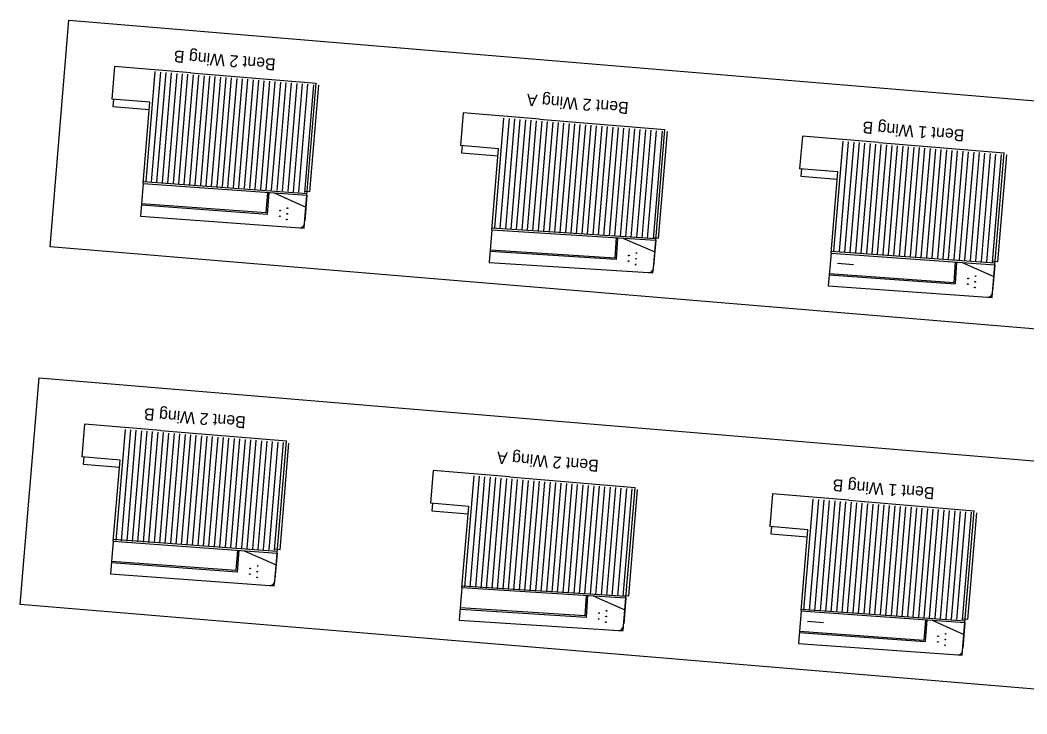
# Model space of a CAD drawing. Extents: x 1313815 to 1314857, y 2089008 to 2089414.
# Drawn here: x 1314567 to 1314659, y 2089331.7 to 2089395.1 of the extents above; entities that cross this region are included whole.
import ezdxf

# ---------------------------------------------------------------- set-up
doc = ezdxf.new("R2010")
doc.units = 0
for name, color, linetype in [('B-Gen-Hidden', 7, 'Continuous'), ('B-Gen-Rebar', 7, 'Continuous'), ('B-Gen-Viewport', 7, 'Continuous'), ('B-Sub-Abutment Cap (Hidden)', 7, 'Continuous'), ('B-Sub-Wingwall', 7, 'Continuous'), ('B-Super-Parapet', 7, 'Continuous')]:
    doc.layers.add(name, color=color, linetype=linetype)

msp = doc.modelspace()

# ---------------------------------------------------------------- linework, layer by layer
at = {"layer": 'B-Gen-Hidden'}
for p, q in [((1314593.477, 2089379.402), (1314594.292, 2089389.161)), ((1314625.332, 2089375.158), (1314626.147, 2089384.917)), ((1314656.32, 2089373.03), (1314657.135, 2089382.789)), ((1314578.254, 2089380.357), (1314593.214, 2089379.263)), ((1314578.24, 2089380.191), (1314593.201, 2089379.097)), ((1314589.585, 2089379.361), (1314589.448, 2089377.491)), ((1314589.71, 2089379.352), (1314589.564, 2089377.358)), ((1314593.477, 2089379.402), (1314592.979, 2089379.444)), ((1314590.208, 2089379.316), (1314593.11, 2089378.017)), ((1314589.564, 2089377.358), (1314578.073, 2089378.198)), ((1314589.448, 2089377.491), (1314578.084, 2089378.323)), ((1314592.542, 2089376.137), (1314592.951, 2089376.107)), ((1314592.951, 2089376.107), (1314592.985, 2089376.518)), ((1314610.095, 2089375.947), (1314625.068, 2089374.996)), ((1314610.109, 2089376.113), (1314625.081, 2089375.163)), ((1314621.449, 2089375.226), (1314621.33, 2089373.355)), ((1314621.574, 2089375.218), (1314621.447, 2089373.222)), ((1314622.073, 2089375.187), (1314624.977, 2089373.917)), ((1314625.332, 2089375.158), (1314624.834, 2089375.2)), ((1314621.447, 2089373.222), (1314609.928, 2089373.954)), ((1314621.33, 2089373.355), (1314609.939, 2089374.078)), ((1314641.097, 2089373.985), (1314656.059, 2089372.912)), ((1314641.083, 2089373.819), (1314656.046, 2089372.746)), ((1314652.431, 2089373.005), (1314652.297, 2089371.135)), ((1314652.556, 2089372.996), (1314652.413, 2089371.002)), ((1314653.053, 2089372.961), (1314655.955, 2089371.667)), ((1314656.32, 2089373.03), (1314655.822, 2089373.071)), ((1314624.409, 2089372.033), (1314624.818, 2089372.007)), ((1314624.818, 2089372.007), (1314624.852, 2089372.414)), ((1314641.663, 2089372.883), (1314643.135, 2089372.76)), ((1314640.917, 2089371.825), (1314652.413, 2089371.002)), ((1314640.927, 2089371.95), (1314652.297, 2089371.135)), ((1314655.796, 2089369.757), (1314655.83, 2089370.169)), ((1314655.387, 2089369.786), (1314655.796, 2089369.757)), ((1314590.747, 2089346.693), (1314591.561, 2089356.452)), ((1314622.602, 2089342.449), (1314623.416, 2089352.208)), ((1314653.59, 2089340.321), (1314654.404, 2089350.079)), ((1314575.509, 2089347.482), (1314590.47, 2089346.388)), ((1314575.523, 2089347.648), (1314590.484, 2089346.554)), ((1314586.855, 2089346.652), (1314586.718, 2089344.782)), ((1314586.979, 2089346.643), (1314586.833, 2089344.648)), ((1314587.478, 2089346.607), (1314590.38, 2089345.308)), ((1314590.747, 2089346.693), (1314590.248, 2089346.735)), ((1314586.833, 2089344.648), (1314575.343, 2089345.489)), ((1314586.718, 2089344.782), (1314575.353, 2089345.613)), ((1314590.221, 2089343.398), (1314590.255, 2089343.809)), ((1314589.811, 2089343.428), (1314590.221, 2089343.398)), ((1314607.364, 2089343.238), (1314622.337, 2089342.287)), ((1314607.378, 2089343.404), (1314622.351, 2089342.453)), ((1314618.719, 2089342.517), (1314618.6, 2089340.646)), ((1314618.844, 2089342.509), (1314618.717, 2089340.513)), ((1314619.343, 2089342.477), (1314622.247, 2089341.208)), ((1314622.602, 2089342.449), (1314622.103, 2089342.491)), ((1314618.717, 2089340.513), (1314607.198, 2089341.244)), ((1314618.6, 2089340.646), (1314607.208, 2089341.369)), ((1314638.353, 2089341.109), (1314653.315, 2089340.037)), ((1314638.366, 2089341.275), (1314653.329, 2089340.203)), ((1314638.933, 2089340.174), (1314640.405, 2089340.051)), ((1314649.701, 2089340.296), (1314649.567, 2089338.426)), ((1314649.826, 2089340.287), (1314649.683, 2089338.292)), ((1314650.323, 2089340.251), (1314653.225, 2089338.957)), ((1314653.59, 2089340.321), (1314653.091, 2089340.362)), ((1314621.678, 2089339.324), (1314622.088, 2089339.298)), ((1314622.088, 2089339.298), (1314622.122, 2089339.705)), ((1314638.186, 2089339.116), (1314649.683, 2089338.292)), ((1314638.197, 2089339.241), (1314649.567, 2089338.426)), ((1314652.656, 2089337.077), (1314653.066, 2089337.047)), ((1314653.066, 2089337.047), (1314653.1, 2089337.46))]:
    msp.add_line(p, q, dxfattribs=at)
at = {"layer": 'B-Gen-Rebar'}
for p, q in [((1314578.505, 2089380.361), (1314579.344, 2089390.409)), ((1314579.004, 2089380.326), (1314579.842, 2089390.367)), ((1314579.502, 2089380.292), (1314580.34, 2089390.326)), ((1314580.001, 2089380.257), (1314580.838, 2089390.284)), ((1314580.5, 2089380.223), (1314581.337, 2089390.243)), ((1314580.999, 2089380.188), (1314581.835, 2089390.201)), ((1314581.498, 2089380.154), (1314582.333, 2089390.159)), ((1314581.997, 2089380.119), (1314582.831, 2089390.118)), ((1314582.496, 2089380.085), (1314583.33, 2089390.076)), ((1314582.995, 2089380.051), (1314583.828, 2089390.035)), ((1314583.493, 2089380.016), (1314584.326, 2089389.993)), ((1314583.992, 2089379.982), (1314584.824, 2089389.951)), ((1314584.491, 2089379.947), (1314585.323, 2089389.91)), ((1314584.99, 2089379.913), (1314585.821, 2089389.868)), ((1314585.489, 2089379.878), (1314586.319, 2089389.827)), ((1314585.988, 2089379.844), (1314586.818, 2089389.785)), ((1314586.487, 2089379.81), (1314587.316, 2089389.743)), ((1314586.985, 2089379.775), (1314587.814, 2089389.702)), ((1314587.484, 2089379.741), (1314588.312, 2089389.66)), ((1314587.983, 2089379.706), (1314588.811, 2089389.619)), ((1314588.482, 2089379.672), (1314589.309, 2089389.577)), ((1314588.981, 2089379.637), (1314589.807, 2089389.535)), ((1314589.48, 2089379.603), (1314590.305, 2089389.494)), ((1314589.979, 2089379.569), (1314590.804, 2089389.452)), ((1314590.478, 2089379.534), (1314591.302, 2089389.411)), ((1314590.976, 2089379.5), (1314591.8, 2089389.369)), ((1314591.475, 2089379.465), (1314592.298, 2089389.328)), ((1314591.974, 2089379.431), (1314592.797, 2089389.286)), ((1314592.473, 2089379.396), (1314593.295, 2089389.244)), ((1314593.793, 2089389.203), (1314592.972, 2089379.362)), ((1314610.36, 2089376.117), (1314611.199, 2089386.165)), ((1314610.859, 2089376.082), (1314611.697, 2089386.123)), ((1314611.358, 2089376.048), (1314612.195, 2089386.082)), ((1314611.856, 2089376.013), (1314612.693, 2089386.04)), ((1314612.355, 2089375.979), (1314613.192, 2089385.999)), ((1314612.854, 2089375.944), (1314613.69, 2089385.957)), ((1314613.353, 2089375.91), (1314614.188, 2089385.915)), ((1314613.852, 2089375.875), (1314614.686, 2089385.874)), ((1314614.351, 2089375.841), (1314615.185, 2089385.832)), ((1314614.85, 2089375.807), (1314615.683, 2089385.791)), ((1314615.348, 2089375.772), (1314616.181, 2089385.749)), ((1314615.847, 2089375.738), (1314616.679, 2089385.707)), ((1314616.346, 2089375.703), (1314617.178, 2089385.666)), ((1314616.845, 2089375.669), (1314617.676, 2089385.624)), ((1314617.344, 2089375.634), (1314618.174, 2089385.583)), ((1314617.843, 2089375.6), (1314618.673, 2089385.541)), ((1314618.342, 2089375.566), (1314619.171, 2089385.499)), ((1314618.84, 2089375.531), (1314619.669, 2089385.458)), ((1314619.339, 2089375.497), (1314620.167, 2089385.416)), ((1314619.838, 2089375.462), (1314620.666, 2089385.375)), ((1314620.337, 2089375.428), (1314621.164, 2089385.333)), ((1314620.836, 2089375.393), (1314621.662, 2089385.291)), ((1314621.335, 2089375.359), (1314622.16, 2089385.25)), ((1314621.834, 2089375.325), (1314622.659, 2089385.208)), ((1314622.333, 2089375.29), (1314623.157, 2089385.167)), ((1314622.831, 2089375.256), (1314623.655, 2089385.125)), ((1314623.33, 2089375.221), (1314624.153, 2089385.084)), ((1314623.829, 2089375.187), (1314624.652, 2089385.042)), ((1314624.328, 2089375.152), (1314625.15, 2089385)), ((1314625.648, 2089384.959), (1314624.827, 2089375.118)), ((1314641.348, 2089373.988), (1314642.187, 2089384.036)), ((1314641.847, 2089373.953), (1314642.685, 2089383.995)), ((1314642.346, 2089373.919), (1314643.183, 2089383.953)), ((1314642.844, 2089373.885), (1314643.681, 2089383.912)), ((1314643.343, 2089373.85), (1314644.18, 2089383.87)), ((1314643.842, 2089373.816), (1314644.678, 2089383.828)), ((1314644.341, 2089373.781), (1314645.176, 2089383.787)), ((1314644.84, 2089373.747), (1314645.675, 2089383.745)), ((1314645.339, 2089373.712), (1314646.173, 2089383.704)), ((1314645.838, 2089373.678), (1314646.671, 2089383.662)), ((1314646.337, 2089373.644), (1314647.169, 2089383.62)), ((1314646.835, 2089373.609), (1314647.668, 2089383.579)), ((1314647.334, 2089373.575), (1314648.166, 2089383.537)), ((1314647.833, 2089373.54), (1314648.664, 2089383.496)), ((1314648.332, 2089373.506), (1314649.162, 2089383.454)), ((1314648.831, 2089373.471), (1314649.661, 2089383.412)), ((1314649.33, 2089373.437), (1314650.159, 2089383.371)), ((1314649.829, 2089373.403), (1314650.657, 2089383.329)), ((1314650.327, 2089373.368), (1314651.155, 2089383.288)), ((1314650.826, 2089373.334), (1314651.654, 2089383.246)), ((1314651.325, 2089373.299), (1314652.152, 2089383.204)), ((1314651.824, 2089373.265), (1314652.65, 2089383.163)), ((1314652.323, 2089373.23), (1314653.149, 2089383.121)), ((1314652.822, 2089373.196), (1314653.647, 2089383.08)), ((1314653.321, 2089373.162), (1314654.145, 2089383.038)), ((1314653.82, 2089373.127), (1314654.643, 2089382.997)), ((1314654.318, 2089373.093), (1314655.142, 2089382.955)), ((1314654.817, 2089373.058), (1314655.64, 2089382.913)), ((1314655.316, 2089373.024), (1314656.138, 2089382.872)), ((1314656.636, 2089382.83), (1314655.815, 2089372.989)), ((1314575.766, 2089347.549), (1314576.613, 2089357.7)), ((1314576.265, 2089347.519), (1314577.111, 2089357.658)), ((1314576.764, 2089347.488), (1314577.61, 2089357.616)), ((1314577.263, 2089347.457), (1314578.108, 2089357.575)), ((1314577.763, 2089347.426), (1314578.606, 2089357.533)), ((1314578.262, 2089347.395), (1314579.105, 2089357.492)), ((1314578.761, 2089347.364), (1314579.603, 2089357.45)), ((1314579.26, 2089347.333), (1314580.101, 2089357.409)), ((1314579.759, 2089347.302), (1314580.599, 2089357.367)), ((1314580.258, 2089347.271), (1314581.098, 2089357.325)), ((1314580.757, 2089347.24), (1314581.596, 2089357.284)), ((1314581.257, 2089347.209), (1314582.094, 2089357.242)), ((1314581.756, 2089347.178), (1314582.592, 2089357.201)), ((1314582.255, 2089347.147), (1314583.091, 2089357.159)), ((1314582.754, 2089347.116), (1314583.589, 2089357.117)), ((1314583.253, 2089347.085), (1314584.087, 2089357.076)), ((1314583.752, 2089347.054), (1314584.585, 2089357.034)), ((1314584.252, 2089347.023), (1314585.084, 2089356.993)), ((1314584.751, 2089346.992), (1314585.582, 2089356.951)), ((1314585.25, 2089346.961), (1314586.08, 2089356.909)), ((1314585.749, 2089346.93), (1314586.579, 2089356.868)), ((1314586.248, 2089346.899), (1314587.077, 2089356.826)), ((1314586.747, 2089346.868), (1314587.575, 2089356.785)), ((1314587.246, 2089346.837), (1314588.073, 2089356.743)), ((1314587.746, 2089346.806), (1314588.572, 2089356.701)), ((1314588.245, 2089346.775), (1314589.07, 2089356.66)), ((1314588.744, 2089346.745), (1314589.568, 2089356.618)), ((1314589.243, 2089346.714), (1314590.066, 2089356.577)), ((1314589.742, 2089346.683), (1314590.565, 2089356.535)), ((1314590.241, 2089346.652), (1314591.063, 2089356.493)), ((1314607.621, 2089343.305), (1314608.468, 2089353.456)), ((1314608.12, 2089343.275), (1314608.966, 2089353.414)), ((1314608.619, 2089343.244), (1314609.465, 2089353.372)), ((1314609.118, 2089343.213), (1314609.963, 2089353.331)), ((1314609.618, 2089343.182), (1314610.461, 2089353.289)), ((1314610.117, 2089343.151), (1314610.96, 2089353.248)), ((1314610.616, 2089343.12), (1314611.458, 2089353.206)), ((1314611.115, 2089343.089), (1314611.956, 2089353.165)), ((1314611.614, 2089343.058), (1314612.454, 2089353.123)), ((1314612.113, 2089343.027), (1314612.953, 2089353.081)), ((1314612.612, 2089342.996), (1314613.451, 2089353.04)), ((1314613.112, 2089342.965), (1314613.949, 2089352.998)), ((1314613.611, 2089342.934), (1314614.447, 2089352.957)), ((1314614.11, 2089342.903), (1314614.946, 2089352.915)), ((1314614.609, 2089342.872), (1314615.444, 2089352.873)), ((1314615.108, 2089342.841), (1314615.942, 2089352.832)), ((1314615.607, 2089342.81), (1314616.44, 2089352.79)), ((1314616.107, 2089342.779), (1314616.939, 2089352.749)), ((1314616.606, 2089342.748), (1314617.437, 2089352.707)), ((1314617.105, 2089342.717), (1314617.935, 2089352.665)), ((1314617.604, 2089342.686), (1314618.434, 2089352.624)), ((1314618.103, 2089342.655), (1314618.932, 2089352.582)), ((1314618.602, 2089342.624), (1314619.43, 2089352.541)), ((1314619.102, 2089342.593), (1314619.928, 2089352.499)), ((1314619.601, 2089342.562), (1314620.427, 2089352.457)), ((1314620.1, 2089342.532), (1314620.925, 2089352.416)), ((1314620.599, 2089342.501), (1314621.423, 2089352.374)), ((1314621.098, 2089342.47), (1314621.921, 2089352.333)), ((1314621.597, 2089342.439), (1314622.42, 2089352.291)), ((1314622.096, 2089342.408), (1314622.918, 2089352.25)), ((1314638.609, 2089341.177), (1314639.456, 2089351.327)), ((1314639.108, 2089341.146), (1314639.955, 2089351.285)), ((1314639.607, 2089341.115), (1314640.453, 2089351.244)), ((1314640.107, 2089341.084), (1314640.951, 2089351.202)), ((1314640.606, 2089341.053), (1314641.449, 2089351.161)), ((1314641.105, 2089341.022), (1314641.948, 2089351.119)), ((1314641.604, 2089340.991), (1314642.446, 2089351.078)), ((1314642.103, 2089340.96), (1314642.944, 2089351.036)), ((1314642.602, 2089340.929), (1314643.442, 2089350.994)), ((1314643.101, 2089340.898), (1314643.941, 2089350.953)), ((1314643.601, 2089340.867), (1314644.439, 2089350.911)), ((1314644.1, 2089340.836), (1314644.937, 2089350.87)), ((1314644.599, 2089340.805), (1314645.436, 2089350.828)), ((1314645.098, 2089340.774), (1314645.934, 2089350.786)), ((1314645.597, 2089340.743), (1314646.432, 2089350.745)), ((1314646.096, 2089340.712), (1314646.93, 2089350.703)), ((1314646.596, 2089340.682), (1314647.429, 2089350.662)), ((1314647.095, 2089340.651), (1314647.927, 2089350.62)), ((1314647.594, 2089340.62), (1314648.425, 2089350.578)), ((1314648.093, 2089340.589), (1314648.923, 2089350.537)), ((1314648.592, 2089340.558), (1314649.422, 2089350.495)), ((1314649.091, 2089340.527), (1314649.92, 2089350.454)), ((1314649.59, 2089340.496), (1314650.418, 2089350.412)), ((1314650.09, 2089340.465), (1314650.916, 2089350.37)), ((1314650.589, 2089340.434), (1314651.415, 2089350.329)), ((1314651.088, 2089340.403), (1314651.913, 2089350.287)), ((1314651.587, 2089340.372), (1314652.411, 2089350.246)), ((1314652.086, 2089340.341), (1314652.91, 2089350.204)), ((1314652.585, 2089340.31), (1314653.408, 2089350.162)), ((1314653.085, 2089340.279), (1314653.906, 2089350.121))]:
    msp.add_line(p, q, dxfattribs=at)
for centre, radius in [((1314590.75, 2089377.701), 0.0313), ((1314591.432, 2089377.921), 0.0312), ((1314590.719, 2089377.181), 0.0313), ((1314591.368, 2089376.88), 0.0313), ((1314591.4, 2089377.4), 0.0313), ((1314623.299, 2089373.82), 0.0312), ((1314622.586, 2089373.08), 0.0313), ((1314622.617, 2089373.6), 0.0313), ((1314623.267, 2089373.3), 0.0313), ((1314623.235, 2089372.779), 0.0313), ((1314653.607, 2089371.494), 0.0313), ((1314654.257, 2089371.193), 0.0313), ((1314654.289, 2089371.713), 0.0312), ((1314653.576, 2089370.973), 0.0313), ((1314654.225, 2089370.673), 0.0313), ((1314587.988, 2089344.471), 0.0313), ((1314588.02, 2089344.992), 0.0313), ((1314588.67, 2089344.691), 0.0313), ((1314588.701, 2089345.211), 0.0312), ((1314588.638, 2089344.17), 0.0313), ((1314619.887, 2089340.891), 0.0313), ((1314620.568, 2089341.111), 0.0312), ((1314619.855, 2089340.371), 0.0313), ((1314620.505, 2089340.07), 0.0313), ((1314620.537, 2089340.59), 0.0313), ((1314651.558, 2089339.004), 0.0312), ((1314650.845, 2089338.264), 0.0313), ((1314650.877, 2089338.785), 0.0313), ((1314651.495, 2089337.963), 0.0313), ((1314651.527, 2089338.484), 0.0313)]:
    msp.add_circle(centre, radius, dxfattribs=at)
at = {"layer": 'B-Gen-Viewport'}
for points in [[(1314689.435, 2089364.398), (1314569.73, 2089374.39), (1314571.46, 2089395.114), (1314691.165, 2089385.122)], [(1314686.705, 2089331.689), (1314567, 2089341.681), (1314568.729, 2089362.405), (1314688.435, 2089352.413)]]:
    msp.add_lwpolyline(points, close=True, dxfattribs=at)
at = {"layer": 'B-Sub-Wingwall'}
for p, q in [((1314575.62, 2089390.887), (1314575.371, 2089387.897)), ((1314582.596, 2089390.305), (1314575.62, 2089390.887)), ((1314582.596, 2089390.305), (1314594.056, 2089389.348)), ((1314593.201, 2089379.097), (1314594.056, 2089389.348)), ((1314578.859, 2089387.606), (1314575.371, 2089387.897)), ((1314575.537, 2089387.883), (1314575.481, 2089387.219)), ((1314575.481, 2089387.219), (1314578.803, 2089386.942)), ((1314578.24, 2089380.191), (1314578.859, 2089387.606)), ((1314607.475, 2089386.643), (1314607.226, 2089383.653)), ((1314614.451, 2089386.061), (1314607.475, 2089386.643)), ((1314614.451, 2089386.061), (1314625.911, 2089385.104)), ((1314625.068, 2089374.996), (1314625.911, 2089385.104)), ((1314638.464, 2089384.514), (1314638.214, 2089381.525)), ((1314645.439, 2089383.932), (1314638.464, 2089384.514)), ((1314610.714, 2089383.362), (1314607.226, 2089383.653)), ((1314607.392, 2089383.639), (1314607.336, 2089382.975)), ((1314610.095, 2089375.947), (1314610.714, 2089383.362)), ((1314645.439, 2089383.932), (1314656.899, 2089382.975)), ((1314607.336, 2089382.975), (1314610.658, 2089382.698)), ((1314656.046, 2089372.746), (1314656.899, 2089382.975)), ((1314641.702, 2089381.234), (1314638.214, 2089381.525)), ((1314638.38, 2089381.511), (1314638.325, 2089380.847)), ((1314641.083, 2089373.819), (1314641.702, 2089381.234)), ((1314638.325, 2089380.847), (1314641.646, 2089380.569)), ((1314572.89, 2089358.178), (1314572.64, 2089355.188)), ((1314579.866, 2089357.595), (1314572.89, 2089358.178)), ((1314579.866, 2089357.595), (1314591.326, 2089356.639)), ((1314590.47, 2089346.388), (1314591.326, 2089356.639)), ((1314576.128, 2089354.897), (1314572.64, 2089355.188)), ((1314572.807, 2089355.174), (1314572.751, 2089354.51)), ((1314575.509, 2089347.482), (1314576.128, 2089354.897)), ((1314572.751, 2089354.51), (1314576.073, 2089354.233)), ((1314604.745, 2089353.934), (1314604.496, 2089350.944)), ((1314611.721, 2089353.351), (1314604.745, 2089353.934)), ((1314611.721, 2089353.351), (1314623.181, 2089352.395)), ((1314622.337, 2089342.287), (1314623.181, 2089352.395)), ((1314635.733, 2089351.805), (1314635.484, 2089348.815)), ((1314642.709, 2089351.223), (1314635.733, 2089351.805)), ((1314607.983, 2089350.653), (1314604.496, 2089350.944)), ((1314604.662, 2089350.93), (1314604.606, 2089350.266)), ((1314642.709, 2089351.223), (1314654.169, 2089350.266)), ((1314604.606, 2089350.266), (1314607.928, 2089349.989)), ((1314607.364, 2089343.238), (1314607.983, 2089350.653)), ((1314653.315, 2089340.037), (1314654.169, 2089350.266)), ((1314638.971, 2089348.524), (1314635.484, 2089348.815)), ((1314635.65, 2089348.802), (1314635.594, 2089348.137)), ((1314635.594, 2089348.137), (1314638.916, 2089347.86)), ((1314638.353, 2089341.109), (1314638.971, 2089348.524))]:
    msp.add_line(p, q, dxfattribs=at)
for centre in [(1314592.57, 2089376.553), (1314624.437, 2089372.449), (1314655.415, 2089370.202), (1314589.84, 2089343.844), (1314621.706, 2089339.739), (1314652.685, 2089337.492)]:
    msp.add_arc(centre, 0.417, 266.10988, 355.22842, dxfattribs=at)
at = {"layer": 'B-Super-Parapet'}
for p, q in [((1314578.24, 2089380.191), (1314577.99, 2089377.202)), ((1314592.985, 2089376.518), (1314593.201, 2089379.097)), ((1314593.201, 2089379.097), (1314593.003, 2089376.729)), ((1314577.99, 2089377.202), (1314592.542, 2089376.137)), ((1314610.095, 2089375.947), (1314609.845, 2089372.958)), ((1314624.852, 2089372.414), (1314625.068, 2089374.996)), ((1314625.068, 2089374.996), (1314624.87, 2089372.628)), ((1314609.845, 2089372.958), (1314624.412, 2089372.033)), ((1314641.083, 2089373.819), (1314640.833, 2089370.829)), ((1314655.83, 2089370.169), (1314656.046, 2089372.746)), ((1314656.046, 2089372.746), (1314655.848, 2089370.378)), ((1314656.046, 2089372.746), (1314655.955, 2089371.667)), ((1314640.833, 2089370.829), (1314655.387, 2089369.786)), ((1314575.509, 2089347.482), (1314575.26, 2089344.492)), ((1314590.255, 2089343.809), (1314590.47, 2089346.388)), ((1314590.47, 2089346.388), (1314590.273, 2089344.02)), ((1314575.26, 2089344.492), (1314589.811, 2089343.428)), ((1314607.364, 2089343.238), (1314607.115, 2089340.248)), ((1314622.122, 2089339.705), (1314622.337, 2089342.287)), ((1314622.337, 2089342.287), (1314622.14, 2089339.919)), ((1314638.353, 2089341.109), (1314638.103, 2089338.12)), ((1314607.115, 2089340.248), (1314621.682, 2089339.323)), ((1314653.1, 2089337.46), (1314653.315, 2089340.037)), ((1314653.315, 2089340.037), (1314653.118, 2089337.669)), ((1314653.315, 2089340.037), (1314653.225, 2089338.957)), ((1314638.103, 2089338.12), (1314652.656, 2089337.077))]:
    msp.add_line(p, q, dxfattribs=at)

# ---------------------------------------------------------------- texts
at = {"layer": 'B-Sub-Abutment Cap (Hidden)'}
for s, p in [('Bent 2 Wing B', (1314590.375, 2089391.583)), ('Bent 2 Wing A', (1314622.626, 2089387.605)), ('Bent 1 Wing B', (1314653.293, 2089385.092)), ('Bent 2 Wing B', (1314587.645, 2089358.873)), ('Bent 2 Wing A', (1314619.896, 2089354.895)), ('Bent 1 Wing B', (1314650.563, 2089352.383))]:
    msp.add_text(s, height=1.09106, rotation=175.22842, dxfattribs=at).set_placement(p)

doc.saveas('drawing.dxf')
